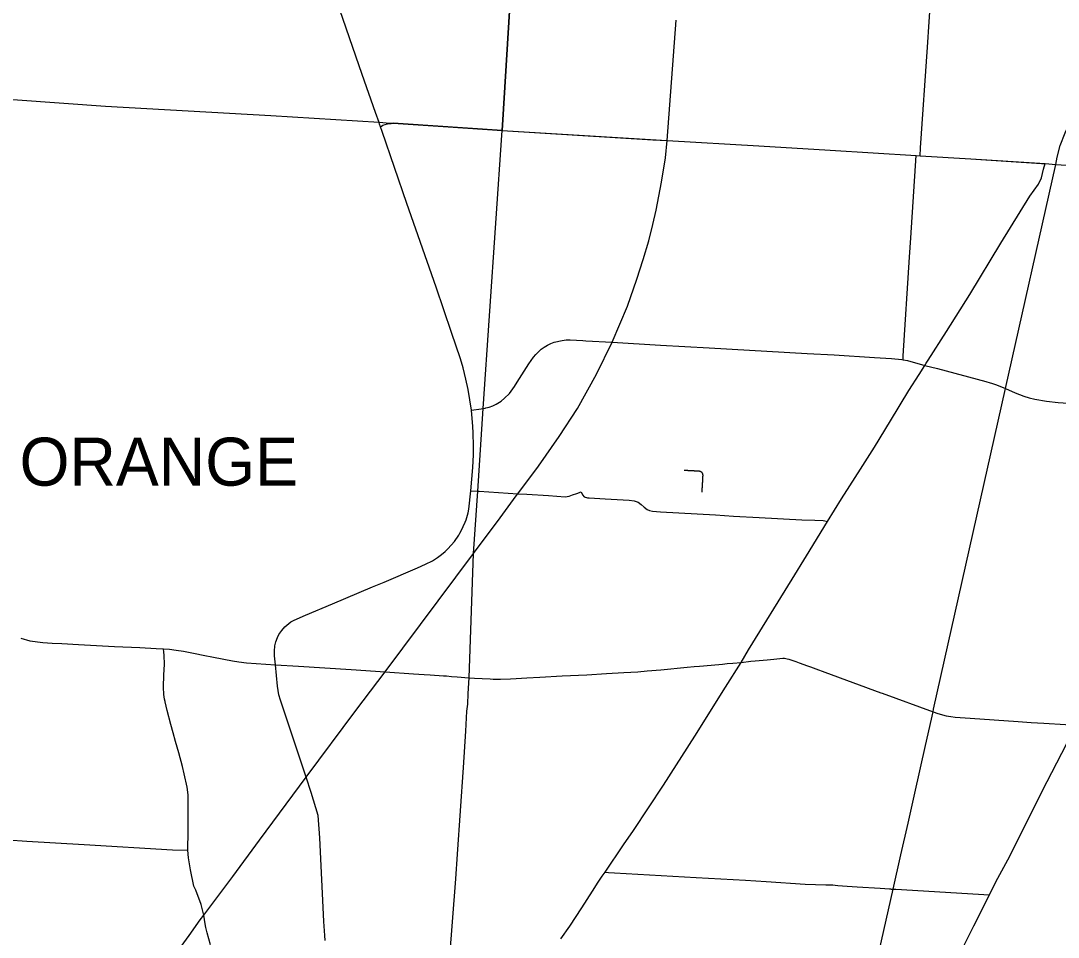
# Model space of a CAD drawing. Extents: x 1729596 to 1925846, y 659247 to 911751.
# Drawn here: x 1836127 to 1855559, y 790063 to 807237 of the extents above; entities that cross this region are included whole.
import ezdxf

# ---------------------------------------------------------------- set-up
doc = ezdxf.new("R2010")
doc.units = 0
for name, color, linetype in [('GM_X_County_Road', 7, 'Continuous'), ('GM_X_Interstate_Route', 7, 'Continuous'), ('GM_X_State_Route', 7, 'Continuous'), ('GM_X_Township', 7, 'Continuous'), ('GM_X_Township_Road', 7, 'Continuous'), ('GM_X_Township_Text', 7, 'Continuous')]:
    doc.layers.add(name, color=color, linetype=linetype)

msp = doc.modelspace()

# ---------------------------------------------------------------- linework, layer by layer
at = {"layer": 'GM_X_County_Road'}
for points in [[(1852972, 804706), (1852981, 804856), (1853110, 806745), (1853175, 807697), (1853246, 808714), (1853530, 812876), (1853592, 813742), (1853681, 815234), (1853705, 815613), (1853731, 815995), (1853772, 816725), (1853832, 817646), (1853875, 818312), (1853892, 818538)], [(1842846, 805301), (1842837, 805328), (1842772, 805518), (1842519, 806229), (1841146, 810217), (1840928, 810827), (1840065, 813066), (1839518, 814468), (1839479, 814577), (1839387, 814825), (1839342, 814985), (1839324, 815084), (1839310, 815214), (1839307, 815315), (1839311, 815371), (1839312, 815408), (1839319, 815463), (1839325, 815513), (1839372, 815780)], [(1840901, 795167), (1840881, 795337), (1840878, 795422), (1840883, 795525), (1840907, 795596), (1840936, 795679), (1840963, 795735), (1841015, 795814), (1841074, 795882), (1841146, 795944), (1841188, 795971), (1841250, 796005), (1841459, 796098), (1841963, 796311), (1842716, 796630), (1842931, 796720), (1843559, 796986), (1843706, 797052), (1843837, 797118), (1843932, 797178), (1844005, 797233), (1844075, 797293), (1844123, 797340), (1844188, 797408), (1844248, 797481), (1844329, 797598), (1844353, 797638), (1844376, 797680), (1844415, 797758), (1844451, 797843), (1844467, 797886), (1844494, 797974), (1844505, 798018), (1844519, 798085), (1844557, 798429), (1844595, 798866), (1844607, 799102), (1844608, 799265), (1844601, 799518), (1844595, 799631), (1844566, 799941), (1844505, 800330), (1844464, 800522), (1844412, 800732), (1844363, 800904), (1844193, 801395), (1843910, 802243), (1843360, 803811), (1842894, 805162), (1842863, 805251), (1842846, 805301)], [(1852657, 800886), (1852657, 800961), (1852774, 802805), (1852798, 803172), (1852898, 804710), (1852972, 804706)], [(1844838, 799981), (1844901, 799998), (1844968, 800023), (1845033, 800054), (1845064, 800071), (1845094, 800091), (1845124, 800110), (1845190, 800164), (1845278, 800253), (1845373, 800385), (1845425, 800462), (1845644, 800809), (1845729, 800932), (1845773, 800986), (1845847, 801059), (1845874, 801080), (1845931, 801120), (1845991, 801156), (1846052, 801187), (1846116, 801212), (1846148, 801222), (1846234, 801241), (1846270, 801248), (1846343, 801255), (1846416, 801256), (1846655, 801244)], [(1846655, 801244), (1846713, 801241), (1847205, 801213), (1848107, 801161), (1849018, 801108), (1850858, 801002), (1851359, 800976), (1852118, 800926), (1852433, 800906), (1852629, 800889), (1852657, 800886), (1852736, 800868), (1853063, 800779), (1853297, 800719), (1854203, 800475), (1854282, 800454), (1854310, 800445)], [(1851239, 797854), (1851501, 798281), (1851653, 798524), (1851853, 798834), (1852115, 799249), (1852419, 799742), (1852763, 800311), (1852954, 800610), (1853063, 800779)], [(1854310, 800445), (1854348, 800433), (1854402, 800414), (1854573, 800349)], [(1854573, 800349), (1854755, 800266), (1854914, 800205), (1855015, 800169), (1855118, 800145), (1855340, 800109), (1855555, 800083), (1855746, 800073), (1856041, 800054), (1856308, 800043), (1856579, 800027), (1856677, 800021), (1856906, 800027), (1857196, 800056), (1857340, 800059), (1857473, 800073), (1857580, 800087), (1857682, 800095), (1857756, 800098), (1857798, 800096), (1857874, 800083), (1857988, 800064)], [(1844566, 799941), (1844753, 799964), (1844785, 799970), (1844828, 799978), (1844838, 799981)], [(1846245, 790032), (1846408, 790272), (1846638, 790612), (1846837, 790928), (1846939, 791093), (1847017, 791206), (1847071, 791285), (1847419, 791795), (1847605, 792061), (1848165, 792910), (1848753, 793830), (1849328, 794748), (1849622, 795214), (1849759, 795447), (1850577, 796772), (1850846, 797211), (1851239, 797854)], [(1851209, 784694), (1851326, 784936), (1852148, 786590), (1852443, 787187), (1853141, 788601), (1853675, 789667), (1853798, 789914), (1853979, 790280), (1854272, 790859), (1854392, 791103), (1854649, 791581), (1855260, 792799), (1855898, 794041), (1856273, 794777), (1856673, 795566), (1856869, 795971), (1857028, 796294)], [(1836126, 795665), (1836296, 795616), (1836540, 795586), (1836718, 795575), (1836898, 795565), (1837211, 795550), (1837882, 795514), (1838358, 795490), (1838663, 795475), (1838800, 795467), (1838912, 795460), (1839037, 795444), (1839177, 795424), (1839395, 795378), (1839546, 795348), (1839738, 795311), (1840094, 795242), (1840210, 795224), (1840358, 795207), (1840537, 795193), (1840901, 795167)], [(1841828, 790004), (1841819, 790093), (1841806, 790360), (1841726, 791923), (1841696, 792345), (1841656, 792486), (1841567, 792777), (1841473, 793063), (1841372, 793364), (1841315, 793534), (1841145, 794040), (1840989, 794505), (1840960, 794607), (1840938, 794769), (1840901, 795167)]]:
    msp.add_lwpolyline(points, dxfattribs=at)
at = {"layer": 'GM_X_Interstate_Route'}
for points in [[(1845438, 798374), (1845825, 798892), (1846211, 799449), (1846552, 799972), (1846911, 800613), (1847205, 801213), (1847493, 801891), (1847666, 802395), (1847786, 802765), (1847888, 803110), (1847964, 803419), (1848028, 803685), (1848125, 804211), (1848200, 804670), (1848231, 804991), (1848401, 807248)], [(1837487, 786429), (1837514, 786520), (1837601, 786793), (1837756, 787221), (1837932, 787687), (1838187, 788245), (1838424, 788716), (1838589, 789007), (1838800, 789367), (1839053, 789775), (1839282, 790094), (1839487, 790389), (1839554, 790475), (1839800, 790800), (1840096, 791202), (1840599, 791880), (1841473, 793063), (1842402, 794310), (1842953, 795035), (1844609, 797255), (1845106, 797922), (1845407, 798332)], [(1845407, 798332), (1845438, 798374)]]:
    msp.add_lwpolyline(points, dxfattribs=at)
at = {"layer": 'GM_X_State_Route'}
for points in [[(1853225, 794338), (1854573, 800349), (1855512, 804546), (1855541, 804679), (1855596, 804898), (1855689, 805139), (1855836, 805465), (1855908, 805599), (1856008, 805767), (1856148, 805978), (1856255, 806119), (1856504, 806413), (1857597, 807668), (1858467, 808668), (1858818, 809072), (1859440, 809788), (1860025, 810459)], [(1851027, 784561), (1851027, 784562), (1851101, 784861), (1851390, 786171), (1851399, 786214), (1851899, 788445), (1852470, 790966), (1852613, 791609), (1852746, 792202), (1852871, 792760), (1853072, 793659), (1853214, 794287), (1853225, 794338)]]:
    msp.add_lwpolyline(points, dxfattribs=at)
at = {"layer": 'GM_X_Township'}
for points in [[(1845296, 807619), (1845145, 805182), (1843287, 805303), (1843103, 805315), (1843041, 805313), (1842837, 805328), (1840812, 805456), (1837716, 805633), (1832763, 805986), (1831742, 806059), (1826634, 806376), (1826602, 806370), (1825150, 806460), (1820453, 806733), (1819657, 806793), (1819325, 806814), (1819232, 806820), (1819101, 806829), (1818544, 806864), (1818726, 809558)], [(1843918, 786568), (1844278, 791160), (1844305, 791617), (1844418, 793241), (1844463, 793924), (1844479, 794298), (1844500, 794432), (1844507, 794629), (1844527, 794924), (1844609, 797255), (1844685, 798421), (1844785, 799970), (1845145, 805182), (1848231, 804991), (1849953, 804892), (1851286, 804810), (1852898, 804710), (1852972, 804706), (1853920, 804647), (1855314, 804559), (1855512, 804546), (1855904, 804520)]]:
    msp.add_lwpolyline(points, dxfattribs=at)
at = {"layer": 'GM_X_Township_Road'}
for points in [[(1845145, 805182), (1845296, 807619), (1845333, 808188), (1845336, 808240)], [(1842863, 805251), (1842909, 805278), (1842951, 805293), (1842996, 805306), (1843041, 805313), (1843065, 805314)], [(1843065, 805314), (1843103, 805315), (1843287, 805303), (1844132, 805248)], [(1844132, 805248), (1845145, 805182)], [(1845145, 805182), (1847965, 805008)], [(1847965, 805008), (1848231, 804991), (1849953, 804892), (1851286, 804810), (1852898, 804710)], [(1852972, 804706), (1853920, 804647), (1855248, 804563)], [(1853063, 800779), (1853085, 800818), (1853124, 800877), (1853467, 801413), (1853904, 802110), (1854482, 803071), (1855027, 803947), (1855187, 804174), (1855245, 804296), (1855285, 804458), (1855314, 804559)], [(1855248, 804563), (1855314, 804559), (1855512, 804546)], [(1855512, 804546), (1855904, 804520), (1856177, 804502), (1856300, 804491), (1856579, 804475), (1858107, 804378)], [(1848887, 798403), (1848888, 798408), (1848888, 798411), (1848888, 798413), (1848888, 798415), (1848888, 798418), (1848888, 798420), (1848889, 798423), (1848889, 798425), (1848889, 798427), (1848889, 798430), (1848889, 798432), (1848889, 798435), (1848889, 798437), (1848890, 798440), (1848890, 798442), (1848890, 798444), (1848890, 798447), (1848890, 798449), (1848890, 798452), (1848890, 798454), (1848891, 798457), (1848891, 798459), (1848891, 798461), (1848891, 798464), (1848891, 798466), (1848891, 798469), (1848891, 798471), (1848892, 798473), (1848892, 798476), (1848892, 798478), (1848892, 798481), (1848892, 798483), (1848892, 798486), (1848893, 798488), (1848893, 798491), (1848893, 798493), (1848893, 798496), (1848893, 798498), (1848893, 798501), (1848893, 798503), (1848894, 798506), (1848894, 798508), (1848894, 798511), (1848894, 798513), (1848894, 798516), (1848894, 798518), (1848894, 798521), (1848895, 798523), (1848895, 798526), (1848895, 798528), (1848895, 798531), (1848895, 798533), (1848895, 798535), (1848896, 798538), (1848896, 798540), (1848896, 798543), (1848896, 798545), (1848896, 798548), (1848896, 798550), (1848896, 798553), (1848897, 798555), (1848897, 798558), (1848897, 798560), (1848897, 798563), (1848897, 798565), (1848897, 798568), (1848897, 798570), (1848898, 798573), (1848898, 798575), (1848898, 798578), (1848898, 798580), (1848898, 798583), (1848898, 798585), (1848899, 798588), (1848899, 798590), (1848899, 798593), (1848899, 798595), (1848899, 798598), (1848899, 798600), (1848899, 798603), (1848900, 798605), (1848900, 798608), (1848900, 798610), (1848900, 798612), (1848900, 798615), (1848900, 798617), (1848900, 798620), (1848901, 798622), (1848901, 798625), (1848901, 798627), (1848901, 798630), (1848901, 798632), (1848901, 798635), (1848902, 798637), (1848902, 798640), (1848902, 798642), (1848902, 798645), (1848902, 798647), (1848902, 798650), (1848902, 798652), (1848903, 798655), (1848903, 798657), (1848903, 798660), (1848903, 798662), (1848903, 798665), (1848903, 798667), (1848903, 798670), (1848904, 798672), (1848904, 798675), (1848904, 798677), (1848904, 798680), (1848904, 798682), (1848904, 798685), (1848905, 798687), (1848905, 798690), (1848905, 798692), (1848905, 798694), (1848905, 798697), (1848905, 798699), (1848905, 798702), (1848906, 798704), (1848906, 798707), (1848906, 798709), (1848906, 798712), (1848906, 798714), (1848906, 798715), (1848906, 798716), (1848906, 798718), (1848906, 798719), (1848906, 798720), (1848906, 798722), (1848906, 798723), (1848906, 798724), (1848906, 798725), (1848906, 798727), (1848906, 798728), (1848906, 798729), (1848905, 798731), (1848905, 798732), (1848905, 798733), (1848905, 798734), (1848904, 798736), (1848904, 798737), (1848904, 798738), (1848903, 798740), (1848903, 798741), (1848903, 798742), (1848902, 798743), (1848902, 798745), (1848901, 798746), (1848901, 798747), (1848900, 798748), (1848900, 798749), (1848899, 798751), (1848899, 798752), (1848898, 798753), (1848898, 798754), (1848897, 798755), (1848896, 798756), (1848896, 798758), (1848895, 798759), (1848894, 798760), (1848893, 798761), (1848893, 798762), (1848892, 798763), (1848891, 798764), (1848890, 798765), (1848890, 798766), (1848889, 798767), (1848888, 798768), (1848887, 798769), (1848886, 798770), (1848885, 798771), (1848884, 798772), (1848883, 798773), (1848882, 798774), (1848881, 798775), (1848881, 798775), (1848880, 798776), (1848879, 798777), (1848877, 798778), (1848876, 798779), (1848875, 798780), (1848874, 798780), (1848873, 798781), (1848872, 798782), (1848871, 798782), (1848870, 798783), (1848869, 798784), (1848868, 798784), (1848867, 798785), (1848865, 798786), (1848864, 798786), (1848863, 798787), (1848862, 798787), (1848861, 798788), (1848859, 798788), (1848858, 798789), (1848857, 798789), (1848856, 798790), (1848854, 798790), (1848853, 798791), (1848852, 798791), (1848851, 798791), (1848849, 798792), (1848848, 798792), (1848847, 798792), (1848846, 798792), (1848844, 798793), (1848843, 798793), (1848842, 798793), (1848840, 798793), (1848839, 798793), (1848838, 798794), (1848837, 798794), (1848836, 798794), (1848833, 798794), (1848831, 798794), (1848828, 798794), (1848826, 798794), (1848823, 798794), (1848821, 798795), (1848818, 798795), (1848816, 798795), (1848813, 798795), (1848811, 798795), (1848808, 798795), (1848806, 798796), (1848803, 798796), (1848801, 798796), (1848798, 798796), (1848796, 798796), (1848793, 798796), (1848791, 798796), (1848788, 798797), (1848786, 798797), (1848783, 798797), (1848781, 798797), (1848778, 798797), (1848776, 798797), (1848773, 798797), (1848771, 798798), (1848768, 798798), (1848766, 798798), (1848763, 798798), (1848761, 798798), (1848758, 798798), (1848756, 798799), (1848753, 798799), (1848751, 798799), (1848748, 798799), (1848746, 798799), (1848744, 798799), (1848741, 798799), (1848739, 798800), (1848736, 798800), (1848734, 798800), (1848731, 798800), (1848729, 798800), (1848726, 798800), (1848724, 798801), (1848721, 798801), (1848719, 798801), (1848716, 798801), (1848714, 798801), (1848711, 798801), (1848709, 798801), (1848706, 798802), (1848704, 798802), (1848701, 798802), (1848699, 798802), (1848696, 798802), (1848694, 798802), (1848691, 798802), (1848689, 798803), (1848686, 798803), (1848684, 798803), (1848681, 798803), (1848679, 798803), (1848676, 798803), (1848674, 798804), (1848671, 798804), (1848669, 798804), (1848666, 798804), (1848664, 798804), (1848661, 798804), (1848659, 798804), (1848656, 798805), (1848654, 798805), (1848651, 798805), (1848649, 798805), (1848646, 798805), (1848644, 798805), (1848641, 798805), (1848639, 798806), (1848636, 798806), (1848634, 798806), (1848631, 798806), (1848629, 798806), (1848626, 798806), (1848624, 798807), (1848621, 798807), (1848619, 798807), (1848616, 798807), (1848614, 798807), (1848611, 798807), (1848609, 798807), (1848606, 798808), (1848604, 798808), (1848601, 798808), (1848599, 798808), (1848596, 798808), (1848594, 798808), (1848591, 798808), (1848589, 798809), (1848586, 798809), (1848584, 798809), (1848581, 798809), (1848579, 798809), (1848576, 798809), (1848574, 798810), (1848571, 798810), (1848569, 798810), (1848566, 798810), (1848564, 798810), (1848561, 798810), (1848559, 798810), (1848556, 798811), (1848551, 798811)], [(1844557, 798429), (1844685, 798421), (1844713, 798419)], [(1844713, 798419), (1845438, 798374), (1845605, 798366), (1846010, 798339), (1846326, 798317), (1846396, 798331), (1846458, 798351), (1846539, 798381), (1846621, 798407)], [(1846621, 798407), (1846648, 798353), (1846677, 798319), (1846739, 798297), (1846774, 798295)], [(1846774, 798295), (1847073, 798278), (1847525, 798251), (1847618, 798241), (1847692, 798217), (1847750, 798174), (1847804, 798120), (1847860, 798079), (1847901, 798061), (1847957, 798048), (1848107, 798036), (1849140, 797980), (1849475, 797956), (1849957, 797930), (1850759, 797887), (1851000, 797878), (1851156, 797870), (1851190, 797866), (1851239, 797854)], [(1839023, 793732), (1839022, 793733), (1838980, 793892), (1838938, 794052), (1838872, 794314), (1838831, 794473), (1838829, 794481), (1838820, 794525), (1838813, 794568), (1838807, 794613), (1838802, 794749), (1838809, 794981), (1838817, 795171), (1838814, 795349), (1838809, 795404), (1838800, 795467)], [(1844518, 794925), (1844527, 794924), (1844623, 794916), (1844766, 794911), (1844921, 794904), (1844972, 794902), (1845039, 794901), (1845111, 794902), (1845300, 794907), (1845407, 794912), (1845608, 794925), (1845850, 794939), (1846270, 794960), (1846729, 794982), (1847097, 795005), (1847420, 795024), (1847682, 795038), (1847858, 795053), (1848116, 795077), (1848609, 795123), (1848741, 795134), (1848838, 795144), (1848913, 795150), (1849273, 795182), (1849356, 795191)], [(1849356, 795191), (1849466, 795202), (1849622, 795214), (1849804, 795234), (1849882, 795241), (1850029, 795258), (1850109, 795264), (1850232, 795277), (1850401, 795291), (1850433, 795290), (1850480, 795282), (1850513, 795274), (1850642, 795228), (1850705, 795204), (1850860, 795148), (1850918, 795128), (1851016, 795091), (1851187, 795029), (1852238, 794646), (1852263, 794637)], [(1840901, 795167), (1841330, 795144), (1842317, 795078)], [(1842317, 795078), (1842953, 795035), (1843483, 795000), (1843682, 794987), (1843794, 794978), (1844046, 794963), (1844099, 794959)], [(1844099, 794959), (1844196, 794951), (1844299, 794944), (1844518, 794925)], [(1852263, 794637), (1853214, 794287)], [(1853214, 794287), (1853305, 794256), (1853460, 794213), (1853545, 794199), (1853631, 794186), (1853911, 794167)], [(1853911, 794167), (1854809, 794108), (1855052, 794090), (1855289, 794075), (1855696, 794051), (1855898, 794041), (1856800, 793974), (1856946, 793960)], [(1839261, 792049), (1839264, 792370), (1839264, 792732), (1839243, 792874), (1839189, 793128), (1839156, 793264), (1839087, 793520), (1839023, 793732)], [(1830989, 792193), (1830989, 792193), (1831659, 792153), (1833599, 792034), (1835168, 791938), (1836243, 791862), (1837317, 791801), (1838966, 791703), (1839258, 791696)], [(1839258, 791696), (1839261, 792049)], [(1839580, 790316), (1839554, 790475), (1839505, 790679), (1839409, 790947), (1839371, 791021), (1839307, 791326), (1839267, 791553), (1839258, 791696)], [(1847071, 791285), (1847137, 791277), (1847250, 791272), (1848774, 791185), (1849701, 791130), (1850088, 791107), (1850817, 791057), (1851208, 791046), (1851334, 791044), (1851380, 791042), (1851428, 791036), (1851605, 791018), (1851790, 791011), (1852221, 790984), (1852401, 790971), (1852418, 790969)], [(1852418, 790969), (1852428, 790967), (1852470, 790966), (1852519, 790965), (1854272, 790859)], [(1839679, 789921), (1839616, 790145), (1839591, 790246), (1839580, 790316)]]:
    msp.add_lwpolyline(points, dxfattribs=at)

# ---------------------------------------------------------------- texts
at = {"layer": 'GM_X_Township_Text'}
msp.add_text('ORANGE', height=900, rotation=0, dxfattribs=at).set_placement((1836104, 798525))

doc.saveas('drawing.dxf')
